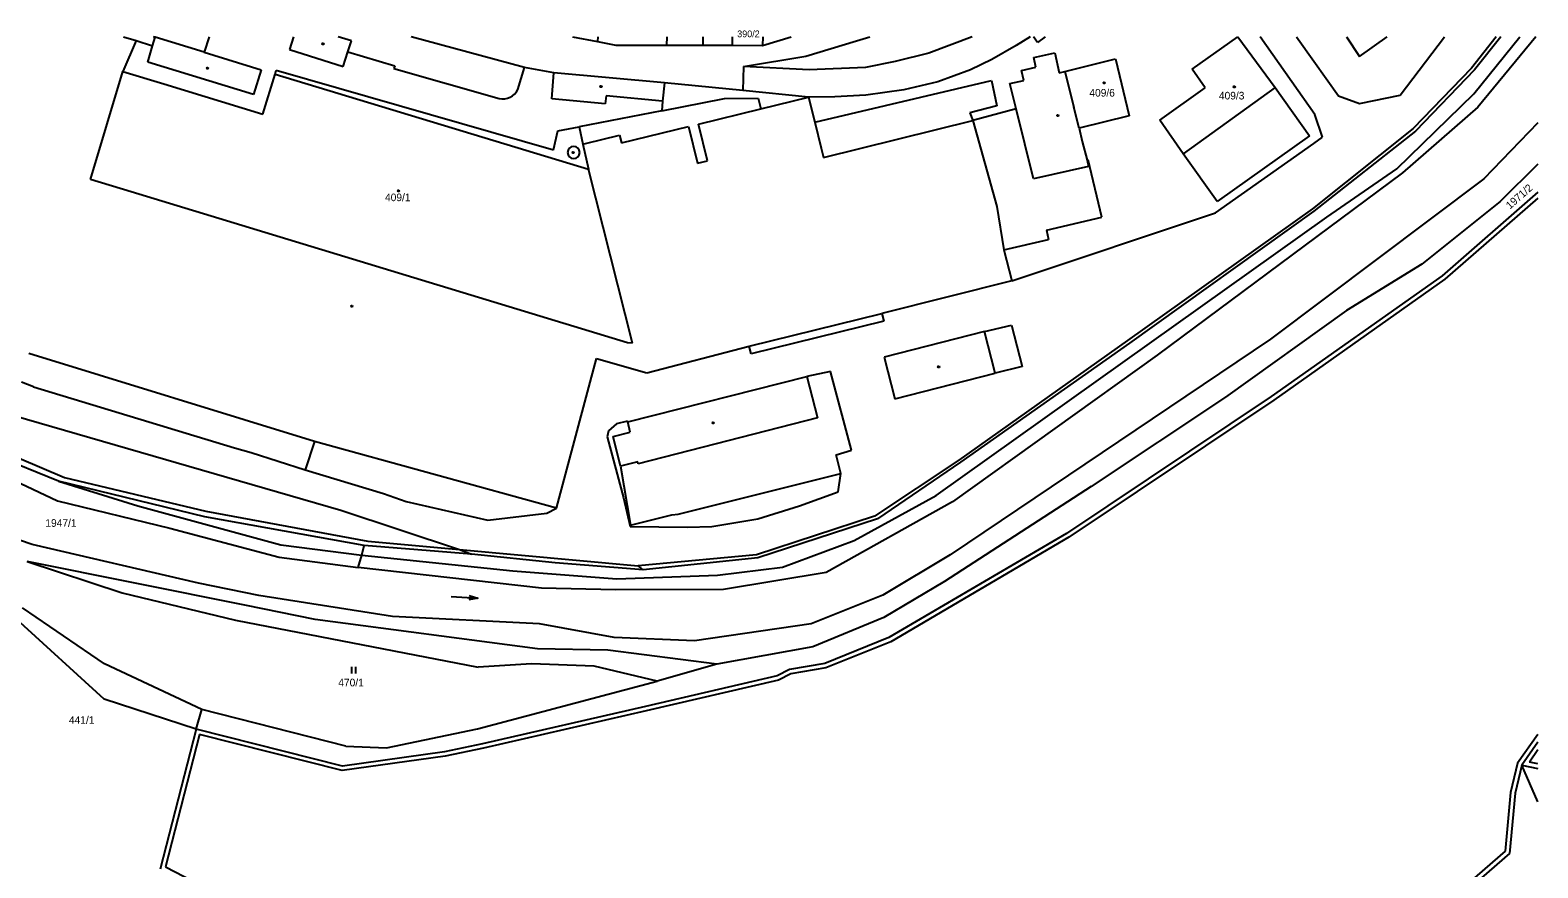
# Model space of a CAD drawing. Extents: x -621797 to -620972, y -1175539 to -1174697.
# Drawn here: x -621313.4 to -620977.2, y -1174884.4 to -1174697.5 of the extents above; entities that cross this region are included whole.
import ezdxf

# ---------------------------------------------------------------- set-up
doc = ezdxf.new("R2010")
doc.units = 0
for name, color, linetype in [('INZ mimo EON - nadz', 7, 'Continuous'), ('Rozvod plynu EON', 7, 'Continuous'), ('SDEL EON', 7, 'Continuous'), ('SDEL EON - popis', 7, 'Continuous'), ('Silnoproud EON', 7, 'Continuous'), ('Silnoproud EON - popis', 7, 'Continuous')]:
    doc.layers.add(name, color=color, linetype=linetype)

msp = doc.modelspace()

# ---------------------------------------------------------------- linework, layer by layer
at = {"layer": 'Rozvod plynu EON'}
for points in [[(-621248.02, -1174700.42), (-621247.93, -1174700.57), (-621248.02, -1174700.72), (-621248.2, -1174700.72), (-621248.29, -1174700.57), (-621248.2, -1174700.42)], [(-621273.78, -1174705.81), (-621273.69, -1174705.96), (-621273.78, -1174706.11), (-621273.96, -1174706.11), (-621274.05, -1174705.96), (-621273.96, -1174705.81)], [(-621186.01, -1174709.88), (-621185.92, -1174710.03), (-621186.01, -1174710.18), (-621186.19, -1174710.18), (-621186.28, -1174710.03), (-621186.19, -1174709.88)], [(-621073.8, -1174709.09), (-621073.71, -1174709.24), (-621073.8, -1174709.39), (-621073.98, -1174709.39), (-621074.07, -1174709.24), (-621073.98, -1174709.09)], [(-621044.76, -1174710.01), (-621044.67, -1174710.16), (-621044.76, -1174710.31), (-621044.94, -1174710.31), (-621045.03, -1174710.16), (-621044.94, -1174710.01)], [(-621084.14, -1174716.35), (-621084.05, -1174716.5), (-621084.14, -1174716.65), (-621084.32, -1174716.65), (-621084.41, -1174716.5), (-621084.32, -1174716.35)], [(-621192.22, -1174724.6), (-621192.13, -1174724.75), (-621192.22, -1174724.9), (-621192.4, -1174724.9), (-621192.49, -1174724.75), (-621192.4, -1174724.6)], [(-621231.17, -1174733.22), (-621231.08, -1174733.37), (-621231.17, -1174733.52), (-621231.35, -1174733.52), (-621231.44, -1174733.37), (-621231.35, -1174733.22)], [(-621241.58, -1174758.88), (-621241.49, -1174759.03), (-621241.58, -1174759.18), (-621241.76, -1174759.18), (-621241.85, -1174759.03), (-621241.76, -1174758.88)], [(-621110.7, -1174772.43), (-621110.61, -1174772.58), (-621110.7, -1174772.73), (-621110.88, -1174772.73), (-621110.97, -1174772.58), (-621110.88, -1174772.43)], [(-621160.99, -1174784.92), (-621160.9, -1174785.07), (-621160.99, -1174785.22), (-621161.17, -1174785.22), (-621161.26, -1174785.07), (-621161.17, -1174784.92)]]:
    msp.add_lwpolyline(points, close=True, dxfattribs=at)
at = {"layer": 'SDEL EON'}
for p, q in [((-621219.523, -1174823.81), (-621213.537, -1174824.23)), ((-621241.78, -1174839.49), (-621241.78, -1174840.99)), ((-621240.78, -1174840.99), (-621240.78, -1174839.49))]:
    msp.add_line(p, q, dxfattribs=at)
msp.add_lwpolyline([(-621215.497, -1174823.591), (-621213.537, -1174824.23), (-621215.568, -1174824.589)], dxfattribs=at)
at = {"layer": 'SDEL EON - popis'}
for p, q in [((-621289.81, -1174699.83), (-621292.73, -1174706.71)), ((-621292.599, -1174698.96), (-621289.81, -1174699.83)), ((-621289.81, -1174699.83), (-621286.1, -1174700.99)), ((-621287.21, -1174704.62), (-621286.1, -1174700.99)), ((-621286.1, -1174700.99), (-621285.52, -1174699.08)), ((-621254.711, -1174698.96), (-621255.61, -1174701.8)), ((-621255.61, -1174701.8), (-621243.59, -1174705.61)), ((-621241.78, -1174699.9), (-621244.738, -1174698.96)), ((-621242.54, -1174702.3), (-621241.78, -1174699.9)), ((-621186.805, -1174698.96), (-621186.86, -1174700.03)), ((-621032.04, -1174709.01), (-621039.08, -1174698.96)), ((-621030.972, -1174698.96), (-621027.09, -1174704.41)), ((-621007.89, -1174712), (-620998.002, -1174698.96)), ((-620986.42, -1174698.96), (-620991.96, -1174705.96)), ((-620991.42, -1174711.66), (-620981.188, -1174698.96)), ((-621263.59, -1174711.86), (-621287.21, -1174704.62)), ((-621274.63, -1174702.43), (-621261.91, -1174706.35)), ((-621243.59, -1174705.61), (-621242.54, -1174702.3)), ((-621242.54, -1174702.3), (-621232.12, -1174705.46)), ((-621089.6, -1174703.6), (-621084.9, -1174702.57)), ((-621089.13, -1174705.77), (-621089.6, -1174703.6)), ((-621084.9, -1174702.57), (-621083.93, -1174707)), ((-621027.09, -1174704.41), (-621021.6, -1174712.12)), ((-621299.97, -1174730.78), (-621292.73, -1174706.71)), ((-621292.73, -1174706.71), (-621283.58, -1174709.5)), ((-621261.91, -1174706.35), (-621263.59, -1174711.86)), ((-621261.52, -1174716.24), (-621258.81, -1174707.29)), ((-621258.81, -1174707.29), (-621258.54, -1174706.43)), ((-621258.81, -1174707.29), (-621188.9, -1174728.49)), ((-621258.54, -1174706.43), (-621196.71, -1174724.22)), ((-621232.12, -1174705.46), (-621232.28, -1174706.04)), ((-621232.28, -1174706.04), (-621208.82, -1174712.72)), ((-621204.66, -1174710.72), (-621203.15, -1174705.83)), ((-621197.09, -1174712.81), (-621196.59, -1174706.99)), ((-621138.4, -1174718.02), (-621099.01, -1174708.73)), ((-621099.01, -1174708.73), (-621097.82, -1174714.37)), ((-621094.89, -1174709.4), (-621091.8, -1174708.73)), ((-621092.3, -1174706.46), (-621089.13, -1174705.77)), ((-621091.8, -1174708.73), (-621092.3, -1174706.46)), ((-621083.93, -1174707), (-621082.64, -1174706.72)), ((-620991.96, -1174705.96), (-621004.94, -1174719.42)), ((-621283.58, -1174709.5), (-621261.52, -1174716.24)), ((-621184.96, -1174712.12), (-621185.14, -1174713.96)), ((-621172.35, -1174713.34), (-621184.96, -1174712.12)), ((-621171.95, -1174709.27), (-621172.35, -1174713.34)), ((-621093.5, -1174715.06), (-621094.89, -1174709.4)), ((-621035.72, -1174710.26), (-621028.09, -1174721.09)), ((-621026.87, -1174716.3), (-621032.04, -1174709.01)), ((-621021.6, -1174712.12), (-621016.94, -1174713.83)), ((-621016.94, -1174713.83), (-621007.89, -1174712)), ((-621008.61, -1174728.45), (-620991.42, -1174711.66)), ((-621185.14, -1174713.96), (-621197.09, -1174712.81)), ((-621172.56, -1174715.46), (-621190.99, -1174719.04)), ((-621172.56, -1174715.46), (-621158.56, -1174712.74)), ((-621172.35, -1174713.34), (-621172.56, -1174715.46)), ((-621164.37, -1174718.44), (-621150.45, -1174715.03)), ((-621158.56, -1174712.74), (-621151.03, -1174712.64)), ((-621151.03, -1174712.64), (-621150.45, -1174715.03)), ((-621150.45, -1174715.03), (-621139.79, -1174712.42)), ((-621139.79, -1174712.42), (-621138.4, -1174718.02)), ((-621097.82, -1174714.37), (-621103.85, -1174715.96)), ((-621093.5, -1174715.06), (-621103.2, -1174717.62)), ((-621089.66, -1174730.69), (-621093.5, -1174715.06)), ((-621162.36, -1174726.64), (-621164.37, -1174718.44)), ((-621138.4, -1174718.02), (-621136.97, -1174723.79)), ((-621136.45, -1174725.88), (-621103.2, -1174717.62)), ((-621103.85, -1174715.96), (-621103.2, -1174717.62)), ((-621103.2, -1174717.62), (-621097.79, -1174736.8)), ((-621025.15, -1174721.38), (-621026.87, -1174716.3)), ((-620977.15, -1174718.133), (-620989.18, -1174730.68)), ((-621196.71, -1174724.22), (-621195.74, -1174719.96)), ((-621195.74, -1174719.96), (-621190.99, -1174719.04)), ((-621190.99, -1174719.04), (-621190.13, -1174722.92)), ((-621189.57, -1174722.78), (-621181.98, -1174720.92)), ((-621181.98, -1174720.92), (-621181.56, -1174722.65)), ((-621181.56, -1174722.65), (-621166.62, -1174718.99)), ((-621166.62, -1174718.99), (-621164.61, -1174727.19)), ((-621079.48, -1174719.38), (-621078.75, -1174722.3)), ((-621028.09, -1174721.09), (-621048.64, -1174735.68)), ((-621004.94, -1174719.42), (-621027.41, -1174737.35)), ((-621027.11, -1174722.75), (-621025.15, -1174721.38)), ((-621190.13, -1174722.92), (-621189.57, -1174722.78)), ((-621190.13, -1174722.92), (-621188.9, -1174728.49)), ((-621136.97, -1174723.79), (-621136.45, -1174725.88)), ((-621078.75, -1174722.3), (-621077.65, -1174726.46)), ((-621048.64, -1174735.68), (-621056.29, -1174725.06)), ((-621049.01, -1174738.27), (-621027.11, -1174722.75)), ((-621179.08, -1174767.28), (-621188.9, -1174728.49)), ((-621164.61, -1174727.19), (-621162.36, -1174726.64)), ((-621077.34, -1174727.94), (-621089.66, -1174730.69)), ((-621077.46, -1174726.41), (-621077.65, -1174726.46)), ((-621077.65, -1174726.46), (-621077.34, -1174727.94)), ((-621074.36, -1174739.18), (-621077.46, -1174726.41)), ((-621024.2, -1174739.21), (-621008.61, -1174728.45)), ((-621290.86, -1174733.55), (-621299.97, -1174730.78)), ((-620989.18, -1174730.68), (-621036.81, -1174766.44)), ((-621180.2, -1174767.24), (-621290.86, -1174733.55)), ((-620977.15, -1174734.998), (-620997.87, -1174753.06)), ((-621097.79, -1174736.8), (-621096.23, -1174746.46)), ((-621094.44, -1174753.42), (-621049.01, -1174738.27)), ((-621027.41, -1174737.35), (-621068.7, -1174766.73)), ((-621086.76, -1174742.1), (-621074.36, -1174739.18)), ((-621086.76, -1174742.1), (-621086.27, -1174744.19)), ((-621063.73, -1174767.39), (-621024.2, -1174739.21)), ((-621096.23, -1174746.46), (-621086.27, -1174744.19)), ((-621096.23, -1174746.46), (-621094.44, -1174753.42)), ((-621094.44, -1174753.42), (-621123.49, -1174760.72)), ((-620997.87, -1174753.06), (-621036.06, -1174780)), ((-621153.05, -1174768), (-621123.49, -1174760.72)), ((-621123.05, -1174762.38), (-621152.64, -1174769.68)), ((-621123.49, -1174760.72), (-621123.05, -1174762.38)), ((-621100.59, -1174764.75), (-621122.92, -1174770.41)), ((-621100.59, -1174764.75), (-621094.53, -1174763.27)), ((-621098.21, -1174774.04), (-621100.59, -1174764.75)), ((-621094.53, -1174763.27), (-621092.16, -1174772.51)), ((-621179.08, -1174767.28), (-621180.2, -1174767.24)), ((-621175.9, -1174773.93), (-621153.05, -1174768)), ((-621152.64, -1174769.68), (-621153.05, -1174768)), ((-621111.35, -1174801.33), (-621063.73, -1174767.39)), ((-621036.81, -1174766.44), (-621108.19, -1174814.51)), ((-621068.7, -1174766.73), (-621106.26, -1174793.38)), ((-621249.98, -1174789.27), (-621313.73, -1174769.59)), ((-621196.05, -1174804.13), (-621187.1, -1174770.7)), ((-621187.1, -1174770.7), (-621175.9, -1174773.93)), ((-621122.92, -1174770.41), (-621120.57, -1174779.7)), ((-621092.16, -1174772.51), (-621098.21, -1174774.04)), ((-621358.21, -1174774.93), (-621305.79, -1174797.28)), ((-621312.71, -1174777.06), (-621315.34, -1174776.05)), ((-621180.15, -1174784.85), (-621140.16, -1174774.78)), ((-621134.88, -1174773.6), (-621140.16, -1174774.78)), ((-621140.16, -1174774.78), (-621137.84, -1174783.97)), ((-621130.26, -1174791.22), (-621134.88, -1174773.6)), ((-621120.57, -1174779.7), (-621098.21, -1174774.04)), ((-621312.71, -1174777.06), (-621267.84, -1174790.63)), ((-621036.06, -1174780), (-621081.78, -1174810.62)), ((-621182.64, -1174785.34), (-621184.44, -1174786.89)), ((-621180.21, -1174784.7), (-621182.64, -1174785.34)), ((-621180.15, -1174784.85), (-621180.21, -1174784.7)), ((-621179.56, -1174787.2), (-621180.15, -1174784.85)), ((-621137.84, -1174783.97), (-621177.78, -1174794.26)), ((-621338, -1174788.06), (-621307.33, -1174802.47)), ((-621249.98, -1174789.27), (-621252.06, -1174795.55)), ((-621196.05, -1174804.13), (-621249.98, -1174789.27)), ((-621184.44, -1174786.89), (-621184.73, -1174788.18)), ((-621184.73, -1174788.18), (-621181.1, -1174801.85)), ((-621183.42, -1174788.17), (-621179.56, -1174787.2)), ((-621181.76, -1174794.76), (-621183.42, -1174788.17)), ((-621267.84, -1174790.63), (-621264.1, -1174791.71)), ((-621264.1, -1174791.71), (-621252.06, -1174795.55)), ((-621133.65, -1174792.21), (-621130.26, -1174791.22)), ((-621132.63, -1174796.41), (-621133.65, -1174792.21)), ((-621252.06, -1174795.55), (-621234.6, -1174800.86)), ((-621177.9, -1174793.79), (-621181.76, -1174794.76)), ((-621181.76, -1174794.76), (-621179.49, -1174807.88)), ((-621177.78, -1174794.26), (-621177.9, -1174793.79)), ((-621106.26, -1174793.38), (-621125.12, -1174805.91)), ((-621307.08, -1174798.09), (-621289.41, -1174803.61)), ((-621305.79, -1174797.28), (-621274.22, -1174804.83)), ((-621168.86, -1174805.46), (-621132.63, -1174796.41)), ((-621133.24, -1174800.48), (-621132.63, -1174796.41)), ((-621307.33, -1174802.47), (-621282.23, -1174808.58)), ((-621234.6, -1174800.86), (-621229.58, -1174802.61)), ((-621229.58, -1174802.61), (-621211.32, -1174806.8)), ((-621181.1, -1174801.85), (-621179.6, -1174808.23)), ((-621141.82, -1174803.62), (-621133.24, -1174800.48)), ((-621129.6, -1174811.37), (-621111.35, -1174801.33)), ((-621289.41, -1174803.61), (-621257.51, -1174812.3)), ((-621274.22, -1174804.83), (-621238.08, -1174811.47)), ((-621211.32, -1174806.8), (-621198.16, -1174805.21)), ((-621198.16, -1174805.21), (-621196.05, -1174804.13)), ((-621179.49, -1174807.88), (-621170.28, -1174805.58)), ((-621170.28, -1174805.58), (-621168.86, -1174805.46)), ((-621125.12, -1174805.91), (-621151.45, -1174814.51)), ((-621151.14, -1174806.48), (-621141.82, -1174803.62)), ((-621312.96, -1174812.22), (-621323.55, -1174808.67)), ((-621282.23, -1174808.58), (-621257.9, -1174815.04)), ((-621179.6, -1174808.23), (-621166.81, -1174808.38)), ((-621166.81, -1174808.38), (-621161.37, -1174808.22)), ((-621161.37, -1174808.22), (-621151.14, -1174806.48)), ((-621275.88, -1174820.87), (-621312.96, -1174812.22)), ((-621257.51, -1174812.3), (-621239.45, -1174814.58)), ((-621238.08, -1174811.47), (-621217.66, -1174813.34)), ((-621145.59, -1174817.27), (-621129.6, -1174811.37)), ((-621081.78, -1174810.62), (-621121.49, -1174833.91)), ((-621265.55, -1174825.79), (-621314.05, -1174816)), ((-621257.9, -1174815.04), (-621240.26, -1174817.34)), ((-621239.45, -1174814.58), (-621205.73, -1174818.08)), ((-621217.66, -1174813.34), (-621177.79, -1174816.98)), ((-621151.45, -1174814.51), (-621177.79, -1174816.98)), ((-621108.19, -1174814.51), (-621123.21, -1174823.54)), ((-621205.73, -1174818.08), (-621182.59, -1174819.91)), ((-621182.59, -1174819.91), (-621160.11, -1174819.05)), ((-621176.71, -1174817.85), (-621177.79, -1174816.98)), ((-621160.11, -1174819.05), (-621145.59, -1174817.27)), ((-621262.45, -1174823.58), (-621275.88, -1174820.87)), ((-621249.88, -1174828.94), (-621265.55, -1174825.79)), ((-621232.63, -1174828.3), (-621262.45, -1174823.58)), ((-621123.21, -1174823.54), (-621139.22, -1174829.95)), ((-621200.23, -1174835.5), (-621249.88, -1174828.94)), ((-621199.84, -1174829.91), (-621232.63, -1174828.3)), ((-621183.16, -1174832.95), (-621199.84, -1174829.91)), ((-621165.21, -1174833.75), (-621183.16, -1174832.95)), ((-621139.22, -1174829.95), (-621165.21, -1174833.75)), ((-621184.59, -1174835.77), (-621200.23, -1174835.5)), ((-621160.25, -1174838.9), (-621184.59, -1174835.77)), ((-621121.49, -1174833.91), (-621135.92, -1174839.76)), ((-621135.92, -1174839.76), (-621143.76, -1174841.05)), ((-621146.49, -1174842.5), (-621175.99, -1174849.31)), ((-621143.76, -1174841.05), (-621146.49, -1174842.5)), ((-621175.99, -1174849.31), (-621212.32, -1174857.66)), ((-621275.64, -1174854.64), (-621283.27, -1174884.1)), ((-621243.81, -1174862.68), (-621275.64, -1174854.64)), ((-620977.15, -1174854.588), (-620981.66, -1174861)), ((-621220.85, -1174859.47), (-621243.81, -1174862.68)), ((-621212.32, -1174857.66), (-621220.85, -1174859.47)), ((-620977.15, -1174858.068), (-620979.04, -1174860.76)), ((-620981.66, -1174861), (-620983.22, -1174867.56)), ((-620977.15, -1174861.162), (-620979.04, -1174860.76)), ((-620983.22, -1174867.56), (-620984.41, -1174880.64)), ((-620984.41, -1174880.64), (-621005.32, -1174898.72)), ((-621283.27, -1174884.1), (-621275.08, -1174888.35))]:
    msp.add_line(p, q, dxfattribs=at)
for centre, radius, start, end in [((-621207.973, -1174709.156), 3.664, 256.63092, 334.72271), ((-621192.2, -1174724.79), 1.36, 0, 180), ((-621192.2, -1174724.79), 1.36, 180, 0)]:
    msp.add_arc(centre, radius, start, end, dxfattribs=at)
at = {"layer": 'Silnoproud EON'}
for p, q in [((-621285.52, -1174699.08), (-621285.908, -1174698.96)), ((-621274.63, -1174702.43), (-621285.52, -1174699.08)), ((-621273.503, -1174698.96), (-621274.63, -1174702.43)), ((-621203.15, -1174705.83), (-621228.444, -1174698.96)), ((-621192.443, -1174698.96), (-621186.86, -1174700.03)), ((-621186.86, -1174700.03), (-621182.82, -1174700.81)), ((-621182.82, -1174700.81), (-621171.48, -1174700.82)), ((-621171.441, -1174698.96), (-621171.48, -1174700.82)), ((-621171.48, -1174700.82), (-621163.42, -1174700.82)), ((-621163.4, -1174698.96), (-621163.42, -1174700.82)), ((-621163.42, -1174700.82), (-621156.77, -1174700.85)), ((-621156.77, -1174700.85), (-621156.759, -1174698.96)), ((-621156.77, -1174700.85), (-621150.09, -1174700.89)), ((-621150.09, -1174700.89), (-621143.659, -1174698.96)), ((-621150.025, -1174698.96), (-621150.09, -1174700.89)), ((-621140.4, -1174703.26), (-621129.11, -1174699.88)), ((-621129.11, -1174699.88), (-621126.133, -1174698.96)), ((-621103.327, -1174698.96), (-621113, -1174702.62)), ((-621093.47, -1174700.88), (-621098.9, -1174704.02)), ((-621090.413, -1174698.96), (-621093.47, -1174700.88)), ((-621088.75, -1174700.26), (-621089.604, -1174698.96)), ((-621087.033, -1174698.96), (-621088.75, -1174700.26)), ((-621054.27, -1174706.22), (-621044.05, -1174698.98)), ((-621044.05, -1174698.98), (-621035.72, -1174710.26)), ((-621019.863, -1174698.96), (-621016.91, -1174703.39)), ((-621016.91, -1174703.39), (-621010.767, -1174698.96)), ((-620985.439, -1174698.96), (-620991.26, -1174706.34)), ((-620977.571, -1174698.96), (-620990.53, -1174714.65)), ((-621154.33, -1174705.57), (-621140.4, -1174703.26)), ((-621120.49, -1174704.47), (-621127.08, -1174705.84)), ((-621113, -1174702.62), (-621120.49, -1174704.47)), ((-621098.9, -1174704.02), (-621103.66, -1174706.37)), ((-621082.64, -1174706.72), (-621071.37, -1174703.9)), ((-621071.37, -1174703.9), (-621068.28, -1174716.58)), ((-621196.59, -1174706.99), (-621203.15, -1174705.83)), ((-621171.95, -1174709.27), (-621196.59, -1174706.99)), ((-621154.33, -1174705.57), (-621154.47, -1174710.98)), ((-621139.69, -1174706.37), (-621154.33, -1174705.57)), ((-621127.08, -1174705.84), (-621139.69, -1174706.37)), ((-621103.66, -1174706.37), (-621110.95, -1174709.04)), ((-621082.64, -1174706.72), (-621080.67, -1174714.64)), ((-621051.32, -1174710.39), (-621054.27, -1174706.22)), ((-620991.26, -1174706.34), (-621004.42, -1174720.01)), ((-621154.47, -1174710.98), (-621171.95, -1174709.27)), ((-621139.79, -1174712.42), (-621154.47, -1174710.98)), ((-621127, -1174712), (-621133.96, -1174712.4)), ((-621118.54, -1174710.82), (-621127, -1174712)), ((-621110.95, -1174709.04), (-621118.54, -1174710.82)), ((-621061.45, -1174717.59), (-621051.32, -1174710.39)), ((-621035.72, -1174710.26), (-621056.29, -1174725.06)), ((-621133.96, -1174712.4), (-621139.79, -1174712.42)), ((-621079.48, -1174719.38), (-621080.67, -1174714.64)), ((-620990.53, -1174714.65), (-621007.32, -1174729.29)), ((-621068.28, -1174716.58), (-621079.48, -1174719.38)), ((-621056.29, -1174725.06), (-621061.45, -1174717.59)), ((-621004.42, -1174720.01), (-621027.08, -1174737.88)), ((-620977.15, -1174727.415), (-620985.54, -1174735.69)), ((-621007.32, -1174729.29), (-621062.08, -1174770.01)), ((-620985.54, -1174735.69), (-621003.05, -1174749.68)), ((-620977.15, -1174733.667), (-620998.49, -1174752.27)), ((-621027.08, -1174737.88), (-621068.21, -1174767.3)), ((-620998.49, -1174752.27), (-621036.63, -1174779.18)), ((-621003.05, -1174749.68), (-621019.86, -1174760.05)), ((-621019.86, -1174760.05), (-621046.84, -1174779.35)), ((-621068.21, -1174767.3), (-621105.93, -1174793.84)), ((-621062.08, -1174770.01), (-621107.73, -1174802.74)), ((-621036.63, -1174779.18), (-621082.31, -1174809.77)), ((-621046.84, -1174779.35), (-621076.76, -1174799.3)), ((-621319.9, -1174782.64), (-621244.1, -1174804.58)), ((-621307.08, -1174798.09), (-621338.51, -1174785.31)), ((-621105.93, -1174793.84), (-621124.45, -1174806.5)), ((-621274.45, -1174806.03), (-621307.08, -1174798.09)), ((-621076.76, -1174799.3), (-621109.48, -1174820.47)), ((-621107.73, -1174802.74), (-621135.89, -1174818.5)), ((-621238.89, -1174812.42), (-621274.45, -1174806.03)), ((-621244.1, -1174804.58), (-621217.66, -1174813.34)), ((-621124.45, -1174806.5), (-621151.11, -1174815.19)), ((-621239.45, -1174814.58), (-621238.89, -1174812.42)), ((-621214.99, -1174814.42), (-621238.89, -1174812.42)), ((-621082.31, -1174809.77), (-621121.93, -1174833.01)), ((-621314.05, -1174816), (-621292.92, -1174822.99)), ((-621240.26, -1174817.34), (-621239.45, -1174814.58)), ((-621217.66, -1174813.34), (-621214.99, -1174814.42)), ((-621196.3, -1174816.31), (-621214.99, -1174814.42)), ((-621176.71, -1174817.85), (-621196.3, -1174816.31)), ((-621151.11, -1174815.19), (-621176.71, -1174817.85)), ((-621199.38, -1174822), (-621240.26, -1174817.34)), ((-621135.89, -1174818.5), (-621158.76, -1174822.3)), ((-621292.92, -1174822.99), (-621267.64, -1174829.1)), ((-621182.86, -1174822.32), (-621199.38, -1174822)), ((-621158.76, -1174822.3), (-621182.86, -1174822.32)), ((-621109.48, -1174820.47), (-621123.04, -1174828.5)), ((-621296.85, -1174838.84), (-621315.09, -1174826.39)), ((-621296.88, -1174846.73), (-621316.47, -1174828.88)), ((-621267.64, -1174829.1), (-621213.46, -1174839.58)), ((-621123.04, -1174828.5), (-621138.87, -1174835.03)), ((-621121.93, -1174833.01), (-621136.19, -1174838.79)), ((-621138.87, -1174835.03), (-621160.25, -1174838.9)), ((-621275.15, -1174849.04), (-621296.85, -1174838.84)), ((-621201.59, -1174838.87), (-621213.46, -1174839.58)), ((-621187.62, -1174839.4), (-621201.59, -1174838.87)), ((-621173.57, -1174842.68), (-621187.62, -1174839.4)), ((-621160.25, -1174838.9), (-621173.57, -1174842.68)), ((-621136.19, -1174838.79), (-621144.09, -1174840.09)), ((-621213.63, -1174853.34), (-621173.57, -1174842.68)), ((-621146.84, -1174841.56), (-621176.21, -1174848.34)), ((-621144.09, -1174840.09), (-621146.84, -1174841.56)), ((-621276.36, -1174853.43), (-621296.88, -1174846.73)), ((-621276.36, -1174853.43), (-621275.15, -1174849.04)), ((-621243.04, -1174857.18), (-621275.15, -1174849.04)), ((-621176.21, -1174848.34), (-621212.54, -1174856.68)), ((-621233.93, -1174857.55), (-621213.63, -1174853.34)), ((-621276.36, -1174853.43), (-621284.44, -1174884.62)), ((-621243.75, -1174861.66), (-621276.36, -1174853.43)), ((-621212.54, -1174856.68), (-621221.02, -1174858.48)), ((-620977.15, -1174856.327), (-620980.73, -1174861.42)), ((-621221.02, -1174858.48), (-621243.75, -1174861.66)), ((-621243.04, -1174857.18), (-621233.93, -1174857.55)), ((-620980.73, -1174861.42), (-620982.23, -1174867.72)), ((-620977.15, -1174869.6), (-620980.73, -1174861.42)), ((-620980.73, -1174861.42), (-620977.15, -1174862.183)), ((-620982.23, -1174867.72), (-620983.45, -1174881.13)), ((-620983.45, -1174881.13), (-621004.97, -1174899.74))]:
    msp.add_line(p, q, dxfattribs=at)

# ---------------------------------------------------------------- texts
at = {"layer": 'INZ mimo EON - nadz'}
msp.add_text('1947/1', height=1.7, dxfattribs=at).set_placement((-621310.027, -1174808.28))
at = {"layer": 'Silnoproud EON - popis'}
for s, height, p in [('390/2', 1.5, (-621155.721, -1174699.07)), ('409/6', 1.7, (-621077.173, -1174712.31)), ('409/3', 1.7, (-621048.283, -1174712.95)), ('409/1', 1.7, (-621234.273, -1174735.64)), ('470/1', 1.7, (-621244.693, -1174843.87)), ('441/1', 1.7, (-621304.773, -1174852.23))]:
    msp.add_text(s, height=height, dxfattribs=at).set_placement(p)
msp.add_text('1971/2', height=1.7, rotation=41.42485, dxfattribs=at).set_placement((-620983.366, -1174737.53))

doc.saveas('drawing.dxf')
